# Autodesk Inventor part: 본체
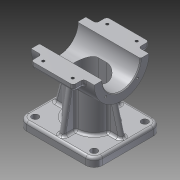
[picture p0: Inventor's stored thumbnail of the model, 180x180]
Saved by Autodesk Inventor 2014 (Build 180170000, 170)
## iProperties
Company: 한국ATC센터
Created: 2014-02
Part Number: 본체
Document SubType Name: Modeling
Designer: KYOUNG IL JANG
Density: 2.71 g/cm^3
Material: 알루미늄-6061
Vendor: CBT Solutions
Mass: 478.987 g
Surface Area: 471.046 cm^2
Volume: 176.748 cm^3
Appearance: 알루미늄 - 평지
Author: KYOUNG IL JANG
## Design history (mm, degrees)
sketch "스케치1"
  geometry: L1 (-45, 40)-(45, 40); L2 (45, 40)-(45, -40); L3 (45, -40)-(-45, -40); L4 (-45, -40)-(-45, 40); 3 further points
  constraints: 8 end point, 2 midpoint, 2 parallel, 1 horizontal, 1 horizontal alignment, 1 perpendicular, 1 vertical alignment
  dimensions: "d0" = 90 distance of L2.end L3.end; "d1" = 80 distance of L1.end L2.end
extrude "돌출1" new body sketch "스케치1" distance "d2" = 10; taper "d3" = 0 deg
sketch "스케치2"
  geometry: L1 (40, 0)-(-40, 0) reference; C1 r 32.5 at (0, 80); 2 further points
  constraints: 1 centre point, 1 midpoint, 1 vertical alignment
  dimensions: "d4" = 65 diameter of C1; "d5" = 80 distance from line of C1.centre L1
extrude "돌출2" join sketch "스케치2" stored distance "d6" = 75; taper "d7" = 0 deg
sketch "스케치3"
  geometry: L1 (-5, -20)-(5, -20); L2 (5, 20)-(-5, 20); A1 r 20 centre (5, 0) between (5, -20) and (5, 20); A2 r 20 centre (-5, 0) between (-5, 20) and (-5, -20); 2 further points
  constraints: 4 end point, 4 point on circle, 4 tangent, 2 centre point, 1 horizontal, 1 horizontal alignment, 1 midpoint, 1 parallel, 1 vertical alignment
  dimensions: "d8" = 20 radius of A2; "d9" = 50 dimension on A1 A2
extrude "돌출3" join sketch "스케치3" stored distance "d10" = 75; taper "d11" = 0 deg
fillet "모깎기1" dims "d12" = 10
sketch "스케치4"
  geometry: L1 (37.5, 47.5)-(-37.5, 47.5) reference; L2 (-40, 10)-(-29.952, 47.5); L3 (-45, 10)-(-35, 10) reference; 1 further point
  constraints: 2 end point, 1 midpoint, 1 point on line
  dimensions: "d105" = 5 distance of L2.start L3.start; "d106" = 75 deg angle of L3 L2
sketch "스케치5"
  geometry: L1 (-35, 10)-(-26.077, 60.603); L2 (-40, 10)-(-30, 10) reference; 2 further points
  constraints: 2 end point, 1 midpoint, 2 other
  dimensions: "d107" = 5 distance of L1.start L2.start; "d108" = 80 deg angle of L2 L1
feature "리브1" dims "d15" = 1, "d16" = 6, "d17" = 0
feature "리브2" dims "d18" = 1, "d19" = 6, "d20" = 0
fillet "모깎기2" dims "d21" = 3
fillet "모깎기3" dims "d22" = 3
fillet "모깎기4" dims "d23" = 3
fillet "모깎기5" dims "d24" = 3
fillet "모깎기6" dims "d25" = 3
fillet "모깎기7" dims "d26" = 3
sketch "스케치6"
  geometry: A1 r 10 centre (35, -30) between (35, -40) and (45, -30) reference; 1 further point
hole "구멍1" sketch "스케치6" at (35, -30) diameter "d28" = 8; stored, may be unused: countersink angle "d32" = 90 deg, drill point angle "d34" = 118 deg; dims "d29" = 6, "d30" = 4, "d31" = 2, "d33" = 8
hole "구멍2" diameter "d37" = 45; stored, may be unused: countersink angle "d41" = 90 deg, drill point angle "d43" = 118 deg; dims "d35" = 10, "d36" = 10, "d38" = 6, "d39" = 4, "d40" = 2, "d42" = 8
sketch "스케치7"
  geometry: C1 r 22.5 at (0, 0) reference; 2 further points
  dimensions: "d44" = 135 deg dimension on C1.centre point (-18.738, 18.738) point (80, 0); "d45" = 26.5 distance of point (-18.738, 18.738) C1.centre
hole "구멍3" sketch "스케치7" at (-18.738, 18.738) diameter "d46" = 2.459; stored, may be unused: countersink angle "d50" = 90 deg, drill point angle "d52" = 118 deg; dims "d47" = 8, "d48" = 4, "d49" = 2, "d51" = 10
node "작업 평면1"
sketch "스케치8"
  geometry: C1 r 10 at (0, 0); 1 further point
  constraints: 1 centre point, 1 coincident
  dimensions: "d57" = 20 diameter of C1
extrude "돌출4" join sketch "스케치8" stored distance "d58" = 75; taper "d59" = 0 deg
hole "구멍4" diameter "d62" = 8.376; stored, may be unused: countersink angle "d66" = 90 deg, drill point angle "d68" = 118 deg; dims "d60" = 10, "d61" = 10, "d63" = 7, "d64" = 4, "d65" = 2, "d67" = 10
chamfer "모따기1" distance "d69" = 1; stored, may be unused: second distance "d70" = 2, angle "d71" = 45 deg
fillet "모깎기9" dims "d72" = 3
sketch "스케치9"
  geometry: L1 (-31.623, 87.5)-(-45, 87.5); L2 (-45, 87.5)-(-45, 72.5); L3 (-45, 72.5)-(-31.623, 72.5); A1 r 32.5 centre (0, 80) between (-31.623, 87.5) and (-31.623, 72.5) reference; 1 further point
  constraints: 6 end point, 2 parallel, 2 point on circle, 1 horizontal, 1 perpendicular
  dimensions: "d73" = 15 distance of L1.end L2.end; "d74" = 45 distance from line of A1.centre L2
extrude "돌출5" join sketch "스케치9" stored distance "d75" = 50; taper "d76" = 0 deg
fillet "모깎기10" dims "d77" = 3
fillet "모깎기11" dims "d78" = 3
sketch "스케치10"
  geometry: L1 (-61.625, 62.366)-(0, 62.366); L2 (0, 62.366)-(0, -62.366); L3 (0, -62.366)-(-61.625, -62.366); L4 (-61.625, -62.366)-(-61.625, 62.366); C1 r 32.5 at (0, 0) reference; 2 further points
  constraints: 8 end point, 2 parallel, 1 coincident, 1 horizontal, 1 midpoint, 1 perpendicular
extrude "돌출6" cut sketch "스케치10" stored distance "d79" = 10; taper "d80" = 0 deg
node "작업 평면2"
sketch "스케치11"
  geometry: L1 (-5, -15)-(5, -15); L2 (5, 15)-(-5, 15); A1 r 15 centre (5, 0) between (5, -15) and (5, 15); A2 r 15 centre (-5, 0) between (-5, 15) and (-5, -15); 9 further points
  constraints: 4 end point, 4 point on circle, 3 tangent, 2 centre point, 1 coincident, 1 horizontal, 1 parallel, 2 other
  dimensions: "d82" = 15 radius of A2; "d109" = 5 dimension on A2; "d110" = 5 dimension on A1
extrude "돌출7" cut sketch "스케치11" stored distance "d83" = 10; taper "d84" = 0 deg
sketch "스케치12"
  geometry: 1 further point
hole "구멍5" sketch "스케치12" at (0, 0) diameter "d85" = 12; stored, may be unused: countersink angle "d89" = 90 deg, drill point angle "d91" = 118 deg; dims "d86" = 6, "d87" = 38, "d88" = 10, "d90" = 8
sketch "스케치13"
  geometry: L1 (-15.5, -12.5)-(-59.5, -12.5) reference; 3 further points
  constraints: 1 horizontal alignment
  dimensions: "d92" = 35 distance of point (-20, -5.5) point (-55, -5.5); "d93" = 17.5 horizontal distance of point (-37.5, 32.5) point (-55, -5.5) (= 0.5 x d92); "d94" = 7 distance from line of L1 point (-55, -5.5)
hole "구멍6" sketch "스케치13" at (-55, -5.5), (-20, -5.5) diameter "d95" = 3.242; stored, may be unused: countersink angle "d99" = 90 deg, drill point angle "d101" = 118 deg; dims "d96" = 6, "d97" = 38, "d98" = 10, "d100" = 8
sketch "스케치14"
  geometry: C1 r 10 at (0, 0); 1 further point
  constraints: 1 centre point, 1 coincident
  dimensions: "d102" = 20 diameter of C1
extrude "돌출8" cut sketch "스케치14" distance "d103" = 5; taper "d104" = 0 deg
fillet "모깎기12" dims "d111" = 3
node "솔리드1"
mirror "대칭1"
mirror "대칭2"
mirror "대칭3"
mirror "대칭4"
pattern_circular "원형 패턴1" dims angle "d54" = 360 deg
mirror "대칭5"
mirror "대칭6"
mirror "대칭7"
other parameters: "d56" = -117
